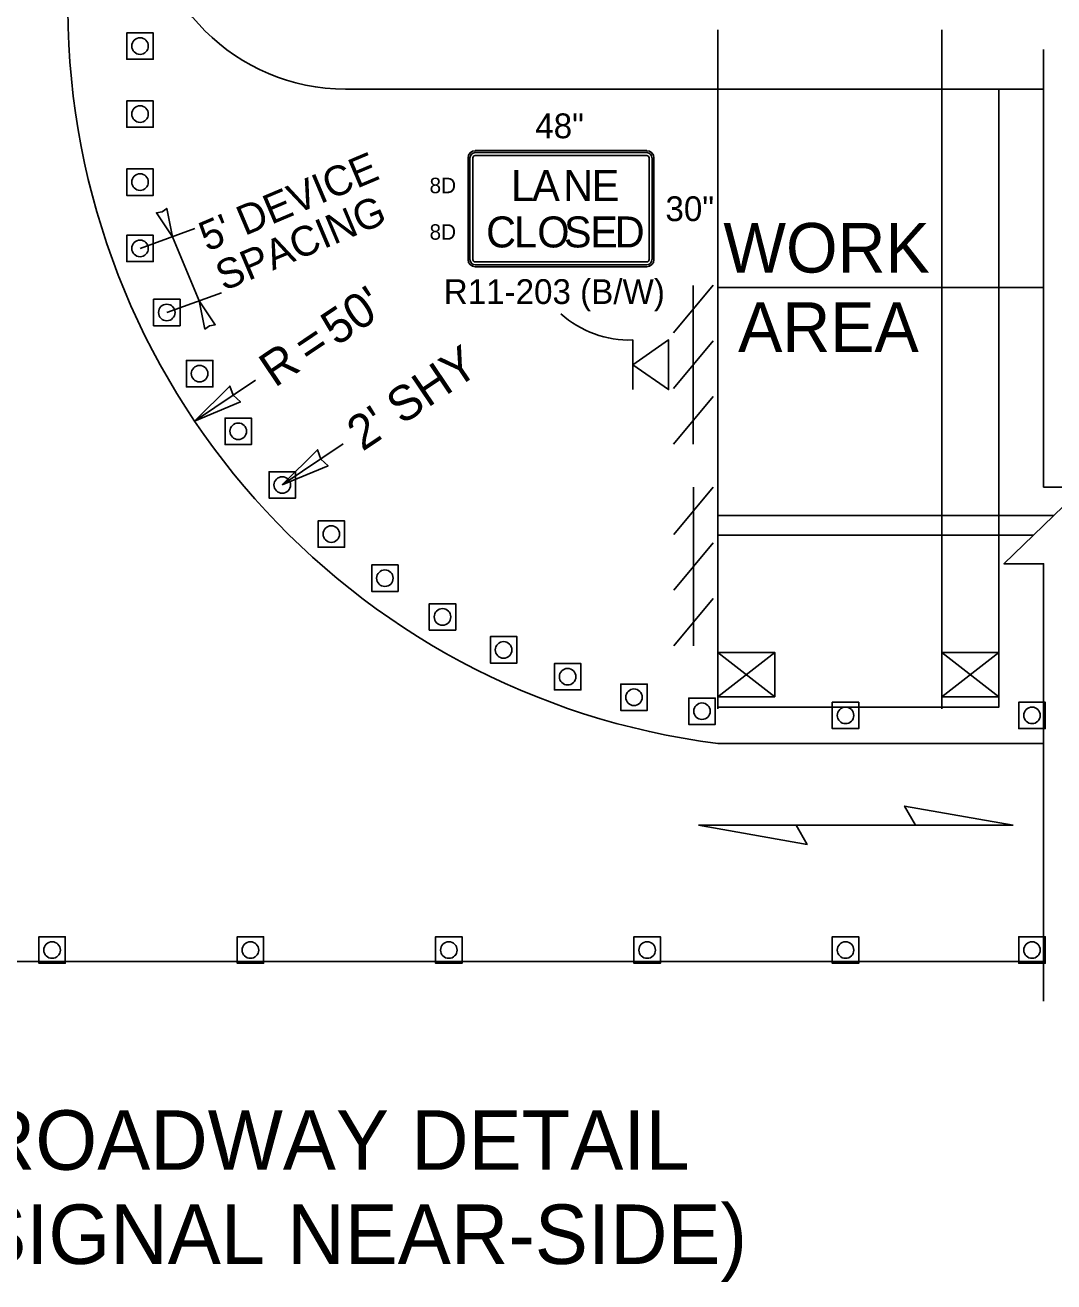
# Model space of a CAD drawing. Extents: x 99979.8 to 100075.7, y 99995 to 100010.7.
# Drawn here: x 100048.321 to 100050.396, y 100001.75 to 100004.285 of the extents above; entities that cross this region are included whole.
import ezdxf

# ---------------------------------------------------------------- set-up
doc = ezdxf.new("R2010")
doc.units = 0
for name, color, linetype in [('RD_ED_ShoulderPavedEdge', 7, 'Continuous'), ('RD_MK_LineDblYellowCenter', 7, 'Continuous'), ('RD_MK_LineEdgeWhite', 7, 'Continuous'), ('RD_MK_LineEdgeWhiteNew', 7, 'Continuous'), ('SH_DE_DetailHeading2Text', 7, 'Continuous'), ('TR_SN_ConstructionSigns', 7, 'Continuous'), ('TR_WZ_BarricadeType3', 7, 'Continuous'), ('TR_WZ_PortableSignMount5ftMinBlk-Wht', 7, 'Continuous'), ('TR_WZ_PortableSignMountBlk-Wht', 7, 'Continuous'), ('TR_WZ_TrafficCone', 7, 'Continuous'), ('TR_WZ_WorkAreaLabel', 7, 'Continuous'), ('TR_WZ_WorkZoneDetails', 7, 'Continuous'), ('TR_WZ_WorkZoneTextCurrent', 7, 'Continuous')]:
    doc.layers.add(name, color=color, linetype=linetype)

msp = doc.modelspace()

# ---------------------------------------------------------------- linework, layer by layer
at = {"layer": 'RD_ED_ShoulderPavedEdge'}
for p, q in [((100048.9675, 100004.1559), (100050.375, 100004.1559)), ((100045.375, 100002.3959), (100050.375, 100002.3959))]:
    msp.add_line(p, q, dxfattribs=at)
msp.add_arc((100048.9675, 100004.5559), 0.4, 180, 270, dxfattribs=at)
at = {"layer": 'RD_MK_LineDblYellowCenter'}
for p, q in [((100049.7179, 100003.2959), (100050.3957, 100003.2959)), ((100049.7179, 100003.2559), (100050.3543, 100003.2559))]:
    msp.add_line(p, q, dxfattribs=at)
at = {"layer": 'RD_MK_LineEdgeWhite'}
for p, q in [((100049.7179, 100003.7559), (100050.375, 100003.7559)), ((100050.375, 100002.8359), (100049.7179, 100002.8359))]:
    msp.add_line(p, q, dxfattribs=at)
at = {"layer": 'RD_MK_LineEdgeWhiteNew'}
msp.add_arc((100049.9075, 100004.3239), 1.5, 180.3046, 262.7399, dxfattribs=at)
at = {"layer": 'TR_SN_ConstructionSigns'}
for p, q in [((100049.229, 100004.0319), (100049.5747, 100004.0319)), ((100049.5747, 100004.0319), (100049.229, 100004.0319)), ((100049.5747, 100004.0319), (100049.229, 100004.0319)), ((100049.5747, 100004.028), (100049.229, 100004.028)), ((100049.229, 100004.0221), (100049.5747, 100004.0221)), ((100049.2144, 100003.8122), (100049.2144, 100004.0172)), ((100049.2144, 100004.0172), (100049.2144, 100003.8122)), ((100049.2144, 100004.0172), (100049.2144, 100003.8122)), ((100049.2183, 100004.0172), (100049.2183, 100003.8122)), ((100049.2241, 100003.8122), (100049.2241, 100004.0172)), ((100049.5796, 100004.0172), (100049.5796, 100003.8122)), ((100049.5855, 100003.8122), (100049.5855, 100004.0172)), ((100049.5894, 100004.0172), (100049.5894, 100003.8122)), ((100049.5894, 100003.8122), (100049.5894, 100004.0172)), ((100049.5894, 100003.8122), (100049.5894, 100004.0172)), ((100049.5747, 100003.8073), (100049.229, 100003.8073)), ((100049.229, 100003.8014), (100049.5747, 100003.8014)), ((100049.5747, 100003.7975), (100049.229, 100003.7975)), ((100049.229, 100003.7975), (100049.5747, 100003.7975)), ((100049.229, 100003.7975), (100049.5747, 100003.7975))]:
    msp.add_line(p, q, dxfattribs=at)
for centre, radius, start, end in [((100049.229, 100004.0172), 0.0146, 90, 180), ((100049.229, 100004.0172), 0.0146, 90, 180), ((100049.229, 100004.0172), 0.0146, 90, 180), ((100049.229, 100004.0172), 0.0107, 90, 180), ((100049.229, 100004.0172), 0.00488, 90, 180), ((100049.5747, 100004.0172), 0.0146, 0, 90), ((100049.5747, 100004.0172), 0.0146, 0, 90), ((100049.5747, 100004.0172), 0.0146, 0, 90), ((100049.5747, 100004.0172), 0.0107, 0, 90), ((100049.5747, 100004.0172), 0.00488, 0, 90), ((100049.229, 100003.8122), 0.0146, 180, 270), ((100049.229, 100003.8122), 0.0146, 180, 270), ((100049.229, 100003.8122), 0.0146, 180, 270), ((100049.229, 100003.8122), 0.0107, 180, 270), ((100049.229, 100003.8122), 0.00488, 180, 270), ((100049.5747, 100003.8122), 0.0107, 270, 0), ((100049.5747, 100003.8122), 0.00488, 270, 0), ((100049.5747, 100003.8122), 0.0146, 270, 0), ((100049.5747, 100003.8122), 0.0146, 270, 0), ((100049.5747, 100003.8122), 0.0146, 270, 0)]:
    msp.add_arc(centre, radius, start, end, dxfattribs=at)
at = {"layer": 'TR_WZ_BarricadeType3'}
for p, q in [((100049.6287, 100003.664), (100049.7087, 100003.7604)), ((100049.6687, 100003.76), (100049.6687, 100003.44)), ((100049.6287, 100003.5518), (100049.7087, 100003.6482)), ((100049.6287, 100003.4396), (100049.7087, 100003.536)), ((100049.6294, 100003.2572), (100049.7087, 100003.3528)), ((100049.669, 100003.3528), (100049.669, 100003.0328)), ((100049.6294, 100003.145), (100049.7087, 100003.2406)), ((100049.6294, 100003.0328), (100049.7087, 100003.1283))]:
    msp.add_line(p, q, dxfattribs=at)
at = {"layer": 'TR_WZ_PortableSignMount5ftMinBlk-Wht'}
for p, q in [((100049.7179, 100003.0438), (100049.7179, 100002.9059)), ((100050.17, 100003.0438), (100050.17, 100002.9059)), ((100049.833, 100002.93), (100049.7179, 100003.0197)), ((100049.833, 100003.0197), (100049.7179, 100002.93)), ((100050.285, 100002.93), (100050.17, 100003.0197)), ((100050.285, 100003.0197), (100050.17, 100002.93)), ((100049.7755, 100002.9749), (100049.7755, 100002.9749)), ((100049.7756, 100002.9748), (100049.7756, 100002.9748)), ((100050.2275, 100002.9749), (100050.2275, 100002.9749)), ((100050.2277, 100002.9748), (100050.2277, 100002.9748))]:
    msp.add_line(p, q, dxfattribs=at)
for points in [[(100049.833, 100002.93), (100049.833, 100003.0197), (100049.7179, 100003.0197), (100049.7179, 100002.93)], [(100050.285, 100002.93), (100050.285, 100003.0197), (100050.17, 100003.0197), (100050.17, 100002.93)]]:
    msp.add_lwpolyline(points, close=True, dxfattribs=at)
at = {"layer": 'TR_WZ_PortableSignMountBlk-Wht'}
msp.add_line((100049.5469, 100003.65), (100049.5469, 100003.55), dxfattribs=at)
msp.add_lwpolyline([(100049.5469, 100003.6001), (100049.6187, 100003.55), (100049.6187, 100003.65)], close=True, dxfattribs=at)
at = {"layer": 'TR_WZ_TrafficCone'}
for points in [[(100048.5798, 100004.2694), (100048.5264, 100004.2694), (100048.5264, 100004.2161), (100048.5798, 100004.2161), (100048.5798, 100004.2694)], [(100048.5798, 100004.2161), (100048.5264, 100004.2161), (100048.5264, 100004.2694), (100048.5798, 100004.2694), (100048.5798, 100004.2161)], [(100048.5798, 100004.1322), (100048.5264, 100004.1322), (100048.5264, 100004.0789), (100048.5798, 100004.0789), (100048.5798, 100004.1322)], [(100048.5798, 100004.0789), (100048.5264, 100004.0789), (100048.5264, 100004.1322), (100048.5798, 100004.1322), (100048.5798, 100004.0789)], [(100048.5798, 100003.9951), (100048.5264, 100003.9951), (100048.5264, 100003.9417), (100048.5798, 100003.9417), (100048.5798, 100003.9951)], [(100048.5798, 100003.9417), (100048.5264, 100003.9417), (100048.5264, 100003.9951), (100048.5798, 100003.9951), (100048.5798, 100003.9417)], [(100048.5798, 100003.8612), (100048.5264, 100003.8612), (100048.5264, 100003.8079), (100048.5798, 100003.8079), (100048.5798, 100003.8612)], [(100048.5798, 100003.8079), (100048.5264, 100003.8079), (100048.5264, 100003.8612), (100048.5798, 100003.8612), (100048.5798, 100003.8079)], [(100048.6337, 100003.732), (100048.5804, 100003.732), (100048.5804, 100003.6787), (100048.6337, 100003.6787), (100048.6337, 100003.732)], [(100048.6337, 100003.6787), (100048.5804, 100003.6787), (100048.5804, 100003.732), (100048.6337, 100003.732), (100048.6337, 100003.6787)], [(100048.6999, 100003.6087), (100048.6466, 100003.6087), (100048.6466, 100003.5553), (100048.6999, 100003.5553), (100048.6999, 100003.6087)], [(100048.6999, 100003.5553), (100048.6466, 100003.5553), (100048.6466, 100003.6087), (100048.6999, 100003.6087), (100048.6999, 100003.5553)], [(100048.7778, 100003.4923), (100048.7244, 100003.4923), (100048.7244, 100003.439), (100048.7778, 100003.439), (100048.7778, 100003.4923)], [(100048.7778, 100003.439), (100048.7244, 100003.439), (100048.7244, 100003.4923), (100048.7778, 100003.4923), (100048.7778, 100003.439)], [(100048.8666, 100003.3841), (100048.8132, 100003.3841), (100048.8132, 100003.3308), (100048.8666, 100003.3308), (100048.8666, 100003.3841)], [(100048.8666, 100003.3308), (100048.8132, 100003.3308), (100048.8132, 100003.3841), (100048.8666, 100003.3841), (100048.8666, 100003.3308)], [(100048.9655, 100003.285), (100048.9121, 100003.285), (100048.9121, 100003.2317), (100048.9655, 100003.2317), (100048.9655, 100003.285)], [(100048.9655, 100003.2317), (100048.9121, 100003.2317), (100048.9121, 100003.285), (100048.9655, 100003.285), (100048.9655, 100003.2317)], [(100049.0735, 100003.196), (100049.0202, 100003.196), (100049.0202, 100003.1426), (100049.0735, 100003.1426), (100049.0735, 100003.196)], [(100049.0735, 100003.1426), (100049.0202, 100003.1426), (100049.0202, 100003.196), (100049.0735, 100003.196), (100049.0735, 100003.1426)], [(100049.1897, 100003.1179), (100049.1364, 100003.1179), (100049.1364, 100003.0645), (100049.1897, 100003.0645), (100049.1897, 100003.1179)], [(100049.1897, 100003.0645), (100049.1364, 100003.0645), (100049.1364, 100003.1179), (100049.1897, 100003.1179), (100049.1897, 100003.0645)], [(100049.3129, 100003.0514), (100049.2596, 100003.0514), (100049.2596, 100002.9981), (100049.3129, 100002.9981), (100049.3129, 100003.0514)], [(100049.3129, 100002.9981), (100049.2596, 100002.9981), (100049.2596, 100003.0514), (100049.3129, 100003.0514), (100049.3129, 100002.9981)], [(100049.442, 100002.9972), (100049.3887, 100002.9972), (100049.3887, 100002.9439), (100049.442, 100002.9439), (100049.442, 100002.9972)], [(100049.442, 100002.9439), (100049.3887, 100002.9439), (100049.3887, 100002.9972), (100049.442, 100002.9972), (100049.442, 100002.9439)], [(100049.5757, 100002.9558), (100049.5224, 100002.9558), (100049.5224, 100002.9025), (100049.5757, 100002.9025), (100049.5757, 100002.9558)], [(100049.5757, 100002.9025), (100049.5224, 100002.9025), (100049.5224, 100002.9558), (100049.5757, 100002.9558), (100049.5757, 100002.9025)], [(100049.7129, 100002.9276), (100049.6595, 100002.9276), (100049.6595, 100002.8743), (100049.7129, 100002.8743), (100049.7129, 100002.9276)], [(100049.7129, 100002.8743), (100049.6595, 100002.8743), (100049.6595, 100002.9276), (100049.7129, 100002.9276), (100049.7129, 100002.8743)], [(100049.949, 100002.9192), (100050.0023, 100002.9192), (100050.0023, 100002.8659), (100049.949, 100002.8659), (100049.949, 100002.9192)], [(100049.949, 100002.8659), (100050.0023, 100002.8659), (100050.0023, 100002.9192), (100049.949, 100002.9192), (100049.949, 100002.8659)], [(100050.325, 100002.9192), (100050.3783, 100002.9192), (100050.3783, 100002.8659), (100050.325, 100002.8659), (100050.325, 100002.9192)], [(100050.325, 100002.8659), (100050.3783, 100002.8659), (100050.3783, 100002.9192), (100050.325, 100002.9192), (100050.325, 100002.8659)], [(100048.349, 100002.4459), (100048.4023, 100002.4459), (100048.4023, 100002.3926), (100048.349, 100002.3926), (100048.349, 100002.4459)], [(100048.349, 100002.3926), (100048.4023, 100002.3926), (100048.4023, 100002.4459), (100048.349, 100002.4459), (100048.349, 100002.3926)], [(100048.749, 100002.4459), (100048.8023, 100002.4459), (100048.8023, 100002.3926), (100048.749, 100002.3926), (100048.749, 100002.4459)], [(100048.749, 100002.3926), (100048.8023, 100002.3926), (100048.8023, 100002.4459), (100048.749, 100002.4459), (100048.749, 100002.3926)], [(100049.149, 100002.4459), (100049.2023, 100002.4459), (100049.2023, 100002.3926), (100049.149, 100002.3926), (100049.149, 100002.4459)], [(100049.149, 100002.3926), (100049.2023, 100002.3926), (100049.2023, 100002.4459), (100049.149, 100002.4459), (100049.149, 100002.3926)], [(100049.549, 100002.4459), (100049.6023, 100002.4459), (100049.6023, 100002.3926), (100049.549, 100002.3926), (100049.549, 100002.4459)], [(100049.549, 100002.3926), (100049.6023, 100002.3926), (100049.6023, 100002.4459), (100049.549, 100002.4459), (100049.549, 100002.3926)], [(100049.949, 100002.4459), (100050.0023, 100002.4459), (100050.0023, 100002.3926), (100049.949, 100002.3926), (100049.949, 100002.4459)], [(100049.949, 100002.3926), (100050.0023, 100002.3926), (100050.0023, 100002.4459), (100049.949, 100002.4459), (100049.949, 100002.3926)], [(100050.325, 100002.4459), (100050.3783, 100002.4459), (100050.3783, 100002.3926), (100050.325, 100002.3926), (100050.325, 100002.4459)], [(100050.325, 100002.3926), (100050.3783, 100002.3926), (100050.3783, 100002.4459), (100050.325, 100002.4459), (100050.325, 100002.3926)]]:
    msp.add_lwpolyline(points, dxfattribs=at)
for centre in [(100048.5531, 100004.2428), (100048.5531, 100004.1056), (100048.5531, 100003.9684), (100048.5531, 100003.8346), (100048.607, 100003.7054), (100048.6732, 100003.582), (100048.7511, 100003.4657), (100048.8399, 100003.3574), (100048.9388, 100003.2583), (100049.0468, 100003.1693), (100049.163, 100003.0912), (100049.2862, 100003.0247), (100049.4153, 100002.9706), (100049.5491, 100002.9292), (100049.6862, 100002.901), (100049.9757, 100002.8926), (100050.3517, 100002.8926), (100048.3757, 100002.4192), (100048.7757, 100002.4192), (100049.1757, 100002.4192), (100049.5757, 100002.4192), (100049.9757, 100002.4192), (100050.3517, 100002.4192)]:
    msp.add_circle(centre, 0.0167, dxfattribs=at)
at = {"layer": 'TR_WZ_WorkZoneDetails'}
for p, q in [((100049.7179, 100004.2759), (100049.7179, 100003.0438)), ((100050.17, 100004.2759), (100050.17, 100003.0438)), ((100048.5532, 100003.8346), (100048.6637, 100003.8745)), ((100048.6184, 100003.8581), (100048.6723, 100003.7289)), ((100048.6071, 100003.7054), (100048.7176, 100003.7453)), ((100048.6632, 100003.4861), (100048.786, 100003.5688)), ((100048.8399, 100003.3574), (100048.9628, 100003.4401)), ((100050.117, 100002.6709), (100049.8759, 100002.6709)), ((100049.8759, 100002.6709), (100050.117, 100002.6709))]:
    msp.add_line(p, q, dxfattribs=at)
msp.add_lwpolyline([(100050.375, 100002.3159), (100050.375, 100003.1985), (100050.295, 100003.1985), (100050.455, 100003.3533), (100050.375, 100003.3533), (100050.375, 100004.2359)], dxfattribs=at)
for points in [[(100050.285, 100004.1559), (100050.285, 100002.9092), (100049.7179, 100002.9092), (100049.7179, 100002.9092), (100049.7179, 100002.9092), (100049.7179, 100002.9092), (100049.7179, 100002.9092), (100049.7179, 100002.9092), (100049.7179, 100002.9092), (100049.7179, 100003.0481), (100049.7179, 100003.1926), (100049.7179, 100003.3574), (100049.7179, 100003.582), (100049.7179, 100003.8346), (100049.7179, 100004.1559)], [(100048.6184, 100003.8581), (100048.5861, 100003.9066), (100048.5974, 100003.9084), (100048.6068, 100003.9152)], [(100048.6723, 100003.7289), (100048.684, 100003.6719), (100048.6933, 100003.6786), (100048.7047, 100003.6805)], [(100048.6632, 100003.4861), (100048.7555, 100003.525), (100048.7409, 100003.5385), (100048.7339, 100003.557)], [(100048.8399, 100003.3574), (100048.9322, 100003.3963), (100048.9177, 100003.4098), (100048.9107, 100003.4283)], [(100050.3136, 100002.6709), (100050.0947, 100002.7095), (100050.117, 100002.6709)], [(100049.6794, 100002.6709), (100049.8982, 100002.6323), (100049.8759, 100002.6709)]]:
    msp.add_lwpolyline(points, close=True, dxfattribs=at)
msp.add_arc((100049.5394, 100003.8558), 0.206, 228.1009, 272.0686, dxfattribs=at)

# ---------------------------------------------------------------- texts
at = {"layer": 'SH_DE_DetailHeading2Text'}
for s, p in [('UNSIGNALIZED INTERSECTING ROADWAY DETAIL', (100045.7563, 100001.9759)), ('SAME SIDE AS LANE CLOSURE (SIGNAL NEAR-SIDE)', (100045.702, 100001.7859))]:
    msp.add_text(s, height=0.12, rotation=360, dxfattribs=at).set_placement(p)
at = {"layer": 'TR_SN_ConstructionSigns'}
for s, p in [('48"', (100049.35, 100004.0569)), ('30"', (100049.6125, 100003.8897)), ('R11-203 (B/W)', (100049.1655, 100003.7225))]:
    msp.add_text(s, height=0.05, rotation=360, dxfattribs=at).set_placement(p)
for s, height, p in [('8D', 0.03125, (100049.1369, 100003.946)), ('L', 0.0625, (100049.3013, 100003.9303)), ('A', 0.0625, (100049.3438, 100003.9303)), ('N', 0.0625, (100049.4063, 100003.9303)), ('E', 0.0625, (100049.4638, 100003.9303)), ('C', 0.0625, (100049.2509, 100003.8366)), ('L', 0.0625, (100049.3072, 100003.8366)), ('O', 0.0625, (100049.3541, 100003.8366)), ('S', 0.0625, (100049.4078, 100003.8366)), ('E', 0.0625, (100049.4609, 100003.8366)), ('D', 0.0625, (100049.5103, 100003.8366)), ('8D', 0.03125, (100049.1369, 100003.8522))]:
    msp.add_text(s, height=height, dxfattribs=at).set_placement(p)
at = {"layer": 'TR_WZ_WorkAreaLabel'}
for s, p in [('WORK', (100049.7294, 100003.7859)), ('AREA', (100049.7591, 100003.6259))]:
    msp.add_text(s, height=0.1, dxfattribs=at).set_placement(p)
at = {"layer": 'TR_WZ_WorkZoneTextCurrent'}
for s, height, rotation, p in [("5' DEVICE", 0.06, 22.8888, (100048.6884, 100003.8275)), ('SPACING', 0.06, 22.8888, (100048.7219, 100003.748)), ("50'", 0.07, 33.9451, (100048.9492, 100003.6364)), ('=', 0.07, 33.9451, (100048.8942, 100003.5994)), ("2' SHY", 0.07, 33.9451, (100049.0016, 100003.424)), ('R', 0.07, 33.9451, (100048.8248, 100003.5527))]:
    msp.add_text(s, height=height, rotation=rotation, dxfattribs=at).set_placement(p)

doc.saveas('drawing.dxf')
